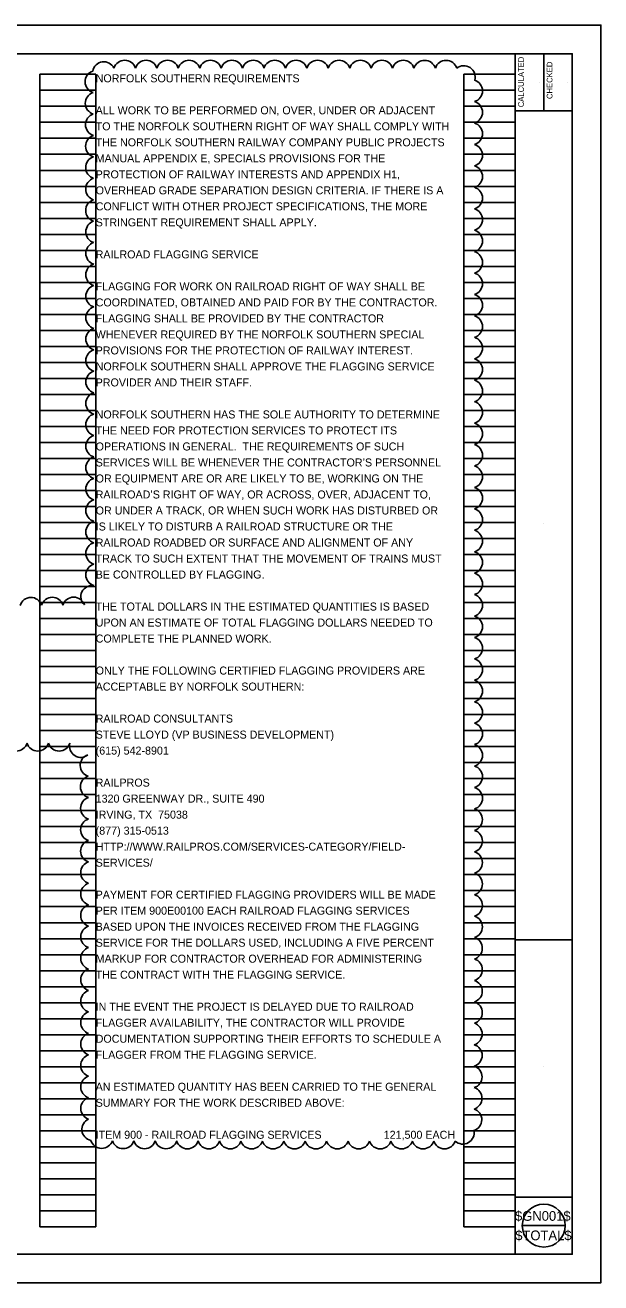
# Model space of a CAD drawing. Extents: x -9 to 100, y -25 to 48.
# Drawn here: x 24.71 to 34.78, y 0.1 to 22.1 of the extents above; entities that cross this region are included whole.
import ezdxf

# ---------------------------------------------------------------- set-up
doc = ezdxf.new("R2010")
doc.units = 0
for name, color, linetype in [('MU_Markup_Cloud', 7, 'Continuous'), ('SH_Border', 7, 'Continuous'), ('SH_Cut_Line', 7, 'Continuous'), ('SH_Data', 7, 'Continuous'), ('SH_Text', 7, 'Continuous')]:
    doc.layers.add(name, color=color, linetype=linetype)

msp = doc.modelspace()

# ---------------------------------------------------------------- linework, layer by layer
at = {"layer": 'MU_Markup_Cloud'}
for centre, radius, start, end in [((26.086, 21.264), 0.196, 25.5249, 170.5249), ((26.451, 21.289), 0.197, 17.5, 162.5), ((26.826, 21.289), 0.197, 17.5, 162.5), ((27.201, 21.289), 0.197, 17.5, 162.5), ((27.576, 21.289), 0.197, 17.5, 162.5), ((27.951, 21.289), 0.197, 17.5, 162.5), ((28.326, 21.289), 0.197, 17.5, 162.5), ((28.701, 21.289), 0.197, 17.5, 162.5), ((29.076, 21.289), 0.197, 17.5, 162.5), ((29.451, 21.289), 0.197, 17.4978, 162.4978), ((29.826, 21.289), 0.197, 17.4937, 162.4937), ((30.201, 21.289), 0.197, 17.4887, 162.4887), ((30.576, 21.289), 0.197, 17.4823, 162.4823), ((30.951, 21.289), 0.197, 17.4738, 162.4738), ((31.325, 21.289), 0.197, 17.4616, 162.4616), ((31.7, 21.288), 0.197, 17.4421, 162.4421), ((32.075, 21.288), 0.197, 17.402, 162.402), ((32.386, 21.194), 0.197, 343.7542, 128.7542), ((25.955, 21.11), 0.197, 108.4583, 253.4583), ((32.515, 20.951), 0.197, 287.5, 72.5), ((25.959, 20.734), 0.197, 107.9402, 252.9402), ((32.515, 20.576), 0.197, 287.5, 72.5), ((25.962, 20.359), 0.197, 107.7909, 252.7909), ((32.515, 20.201), 0.197, 287.5, 72.5), ((25.963, 19.984), 0.197, 107.7103, 252.7103), ((32.515, 19.826), 0.197, 287.5, 72.5), ((25.965, 19.609), 0.197, 107.6578, 252.6578), ((32.515, 19.451), 0.197, 287.5, 72.5), ((25.966, 19.234), 0.197, 107.6202, 252.6202), ((32.515, 19.076), 0.197, 287.5, 72.5), ((25.966, 18.859), 0.197, 107.5914, 252.5914), ((32.515, 18.701), 0.197, 287.5, 72.5), ((25.967, 18.484), 0.197, 107.5685, 252.5685), ((32.515, 18.326), 0.197, 287.5, 72.5), ((25.967, 18.109), 0.197, 107.5498, 252.5498), ((32.515, 17.951), 0.197, 287.5, 72.5), ((25.967, 17.734), 0.197, 107.534, 252.534), ((32.515, 17.577), 0.197, 287.5, 72.5), ((25.968, 17.359), 0.197, 107.5206, 252.5206), ((32.515, 17.202), 0.197, 287.5, 72.5), ((25.968, 16.984), 0.197, 107.5089, 252.5089), ((32.515, 16.827), 0.197, 287.5, 72.5), ((25.968, 16.609), 0.197, 107.5006, 252.5006), ((32.515, 16.452), 0.197, 287.5, 72.5), ((25.968, 16.234), 0.197, 107.5, 252.5), ((32.515, 16.077), 0.197, 287.5, 72.5), ((25.968, 15.859), 0.197, 107.5, 252.5), ((32.515, 15.702), 0.197, 287.5, 72.5), ((25.968, 15.484), 0.197, 107.5, 252.5), ((32.515, 15.327), 0.197, 287.5, 72.5), ((25.968, 15.11), 0.197, 107.5, 252.5), ((32.515, 14.952), 0.197, 287.5, 72.5), ((25.968, 14.735), 0.197, 107.5, 252.5), ((32.515, 14.577), 0.197, 287.5, 72.5), ((25.968, 14.36), 0.197, 107.5, 252.5), ((32.515, 14.202), 0.197, 287.5, 72.5), ((25.968, 13.985), 0.197, 107.5, 252.5), ((32.515, 13.827), 0.197, 287.5, 72.5), ((25.968, 13.61), 0.197, 107.5, 252.5), ((25.968, 13.235), 0.197, 107.5, 252.5), ((32.515, 13.452), 0.197, 287.5, 72.5), ((32.515, 13.077), 0.197, 287.5, 72.5), ((25.968, 12.86), 0.197, 107.5, 252.5), ((32.515, 12.702), 0.197, 287.5, 72.5), ((25.968, 12.485), 0.197, 107.5, 252.5), ((32.515, 12.327), 0.197, 287.5, 72.5), ((25.881, 12.103), 0.197, 81.8355, 226.8355), ((32.515, 11.952), 0.197, 287.4997, 72.4997), ((24.809, 11.893), 0.197, 17.7281, 162.7281), ((25.184, 11.895), 0.197, 17.84, 162.84), ((25.559, 11.898), 0.197, 18.1233, 163.1233), ((32.515, 11.577), 0.197, 287.4976, 72.4976), ((32.515, 11.202), 0.197, 287.4951, 72.4951), ((32.515, 10.828), 0.197, 287.4924, 72.4924), ((32.515, 10.453), 0.197, 287.4895, 72.4895), ((32.515, 10.078), 0.197, 287.4864, 72.4864), ((32.515, 9.703), 0.197, 287.4831, 72.4831), ((24.554, 9.599), 0.197, 197.5, 342.5), ((24.929, 9.599), 0.197, 197.5, 342.5), ((25.304, 9.599), 0.197, 197.5, 342.5), ((25.682, 9.489), 0.197, 165.0186, 310.0186), ((32.515, 9.328), 0.197, 287.4795, 72.4795), ((25.869, 9.152), 0.197, 108.1907, 253.1907), ((32.515, 8.953), 0.197, 287.4756, 72.4756), ((25.873, 8.777), 0.197, 107.8803, 252.8803), ((25.875, 8.402), 0.197, 107.7489, 252.7489), ((32.515, 8.578), 0.197, 287.4713, 72.4713), ((32.514, 8.203), 0.197, 287.4666, 72.4666), ((25.876, 8.027), 0.197, 107.6712, 252.6712), ((32.514, 7.828), 0.197, 287.4614, 72.4614), ((25.877, 7.652), 0.197, 107.6182, 252.6182), ((32.514, 7.453), 0.197, 287.4556, 72.4556), ((25.878, 7.277), 0.197, 107.5791, 252.5791), ((32.514, 7.078), 0.197, 287.4491, 72.4491), ((25.878, 6.902), 0.197, 107.5487, 252.5487), ((32.513, 6.703), 0.197, 287.4418, 72.4418), ((25.878, 6.527), 0.197, 107.5242, 252.5242), ((32.513, 6.328), 0.197, 287.4334, 72.4334), ((25.879, 6.152), 0.197, 107.5047, 252.5047), ((25.879, 5.777), 0.197, 107.5, 252.5), ((32.512, 5.953), 0.197, 287.4235, 72.4235), ((32.512, 5.578), 0.197, 287.4119, 72.4119), ((25.879, 5.402), 0.197, 107.5, 252.5), ((32.511, 5.203), 0.197, 287.3979, 72.3979), ((25.879, 5.027), 0.197, 107.5, 252.5), ((32.511, 4.829), 0.197, 287.3805, 72.3805), ((25.879, 4.652), 0.197, 107.5, 252.5), ((32.51, 4.454), 0.197, 287.358, 72.358), ((25.879, 4.277), 0.197, 107.5, 252.5), ((32.509, 4.079), 0.197, 287.3275, 72.3275), ((25.879, 3.902), 0.197, 107.5, 252.5), ((32.507, 3.704), 0.197, 287.2825, 72.2825), ((25.879, 3.527), 0.197, 107.5, 252.5), ((25.879, 3.152), 0.197, 107.5, 252.5), ((32.506, 3.329), 0.197, 287.2058, 72.2058), ((32.503, 2.954), 0.197, 287.0195, 72.0195), ((25.899, 2.785), 0.197, 113.7583, 258.7583), ((32.368, 2.725), 0.197, 226.9921, 11.9921), ((26.049, 2.649), 0.197, 196.7621, 341.7621), ((26.423, 2.645), 0.197, 197.1919, 342.1919), ((26.798, 2.644), 0.197, 197.3089, 342.3089), ((27.173, 2.643), 0.197, 197.3715, 342.3715), ((27.548, 2.642), 0.197, 197.4121, 342.4121), ((27.923, 2.641), 0.197, 197.4412, 342.4412), ((28.298, 2.641), 0.197, 197.4634, 342.4634), ((28.672, 2.641), 0.197, 197.481, 342.481), ((29.047, 2.641), 0.197, 197.4953, 342.4953), ((29.422, 2.641), 0.197, 197.5, 342.5), ((29.797, 2.641), 0.197, 197.5, 342.5), ((30.172, 2.641), 0.197, 197.5, 342.5), ((30.547, 2.641), 0.197, 197.5, 342.5), ((30.922, 2.641), 0.197, 197.5, 342.5), ((31.297, 2.641), 0.197, 197.5, 342.5), ((31.672, 2.641), 0.197, 197.5, 342.5), ((32.047, 2.641), 0.197, 197.5, 342.5)]:
    msp.add_arc(centre, radius, start, end, dxfattribs=at)
at = {"layer": 'SH_Border'}
for p, q in [((33.283, 0.601), (33.283, 21.601)), ((33.783, 21.601), (33.783, 20.601)), ((33.283, 20.601), (34.283, 20.601)), ((33.283, 6.101), (34.283, 6.101)), ((33.283, 1.601), (34.283, 1.601))]:
    msp.add_line(p, q, dxfattribs=at)
msp.add_lwpolyline([(2.783, 21.601), (34.283, 21.601), (34.283, 0.601), (2.783, 0.601)], close=True, dxfattribs=at)
at = {"layer": 'SH_Cut_Line'}
msp.add_lwpolyline([(0.783, 0.101), (34.783, 0.101), (34.783, 22.101), (0.783, 22.101)], close=True, dxfattribs=at)
at = {"layer": 'SH_Data'}
for p, q in [((24.963, 1.081), (24.963, 21.241)), ((24.963, 21.241), (25.943, 21.241)), ((25.943, 1.081), (25.943, 21.241)), ((32.383, 1.081), (32.383, 21.241)), ((32.383, 21.241), (33.283, 21.241)), ((33.283, 1.081), (33.283, 21.241)), ((24.963, 20.961), (25.943, 20.961)), ((32.383, 20.961), (33.283, 20.961)), ((33.703, 21.104), (33.703, 21.104)), ((34.203, 21.104), (34.203, 21.104)), ((24.963, 20.681), (25.943, 20.681)), ((32.383, 20.681), (33.283, 20.681)), ((24.963, 20.401), (25.943, 20.401)), ((32.383, 20.401), (33.283, 20.401)), ((24.963, 20.121), (25.943, 20.121)), ((32.383, 20.121), (33.283, 20.121)), ((24.963, 19.841), (25.943, 19.841)), ((32.383, 19.841), (33.283, 19.841)), ((24.963, 19.561), (25.943, 19.561)), ((32.383, 19.561), (33.283, 19.561)), ((24.963, 19.281), (25.943, 19.281)), ((32.383, 19.281), (33.283, 19.281)), ((24.963, 19.001), (25.943, 19.001)), ((32.383, 19.001), (33.283, 19.001)), ((24.963, 18.721), (25.943, 18.721)), ((32.383, 18.721), (33.283, 18.721)), ((24.963, 18.441), (25.943, 18.441)), ((32.383, 18.441), (33.283, 18.441)), ((24.963, 18.161), (25.943, 18.161)), ((32.383, 18.161), (33.283, 18.161)), ((24.963, 17.881), (25.943, 17.881)), ((32.383, 17.881), (33.283, 17.881)), ((24.963, 17.601), (25.943, 17.601)), ((32.383, 17.601), (33.283, 17.601)), ((24.963, 17.321), (25.943, 17.321)), ((32.383, 17.321), (33.283, 17.321)), ((24.963, 17.041), (25.943, 17.041)), ((32.383, 17.041), (33.283, 17.041)), ((24.963, 16.761), (25.943, 16.761)), ((32.383, 16.761), (33.283, 16.761)), ((24.963, 16.481), (25.943, 16.481)), ((32.383, 16.481), (33.283, 16.481)), ((24.963, 16.201), (25.943, 16.201)), ((32.383, 16.201), (33.283, 16.201)), ((24.963, 15.921), (25.943, 15.921)), ((32.383, 15.921), (33.283, 15.921)), ((24.963, 15.641), (25.943, 15.641)), ((32.383, 15.641), (33.283, 15.641)), ((24.963, 15.361), (25.943, 15.361)), ((32.383, 15.361), (33.283, 15.361)), ((24.963, 15.081), (25.943, 15.081)), ((32.383, 15.081), (33.283, 15.081)), ((24.963, 14.801), (25.943, 14.801)), ((32.383, 14.801), (33.283, 14.801)), ((24.963, 14.521), (25.943, 14.521)), ((32.383, 14.521), (33.283, 14.521)), ((24.963, 14.241), (25.943, 14.241)), ((32.383, 14.241), (33.283, 14.241)), ((24.963, 13.961), (25.943, 13.961)), ((32.383, 13.961), (33.283, 13.961)), ((24.963, 13.681), (25.943, 13.681)), ((32.383, 13.681), (33.283, 13.681)), ((24.963, 13.401), (25.943, 13.401)), ((32.383, 13.401), (33.283, 13.401)), ((33.783, 13.392), (33.783, 13.392)), ((24.963, 13.121), (25.943, 13.121)), ((32.383, 13.121), (33.283, 13.121)), ((24.963, 12.841), (25.943, 12.841)), ((32.383, 12.841), (33.283, 12.841)), ((24.963, 12.561), (25.943, 12.561)), ((32.383, 12.561), (33.283, 12.561)), ((24.963, 12.281), (25.943, 12.281)), ((32.383, 12.281), (33.283, 12.281)), ((24.963, 12.001), (25.943, 12.001)), ((32.383, 12.001), (33.283, 12.001)), ((24.963, 11.721), (25.943, 11.721)), ((32.383, 11.721), (33.283, 11.721)), ((24.963, 11.441), (25.943, 11.441)), ((32.383, 11.441), (33.283, 11.441)), ((24.963, 11.161), (25.943, 11.161)), ((32.383, 11.161), (33.283, 11.161)), ((24.963, 10.881), (25.943, 10.881)), ((32.383, 10.881), (33.283, 10.881)), ((24.963, 10.601), (25.943, 10.601)), ((32.383, 10.601), (33.283, 10.601)), ((24.963, 10.321), (25.943, 10.321)), ((32.383, 10.321), (33.283, 10.321)), ((24.963, 10.041), (25.943, 10.041)), ((32.383, 10.041), (33.283, 10.041)), ((24.963, 9.761), (25.943, 9.761)), ((32.383, 9.761), (33.283, 9.761)), ((24.963, 9.481), (25.943, 9.481)), ((32.383, 9.481), (33.283, 9.481)), ((24.963, 9.201), (25.943, 9.201)), ((32.383, 9.201), (33.283, 9.201)), ((24.963, 8.921), (25.943, 8.921)), ((32.383, 8.921), (33.283, 8.921)), ((24.963, 8.641), (25.943, 8.641)), ((32.383, 8.641), (33.283, 8.641)), ((24.963, 8.361), (25.943, 8.361)), ((32.383, 8.361), (33.283, 8.361)), ((24.963, 8.081), (25.943, 8.081)), ((32.383, 8.081), (33.283, 8.081)), ((24.963, 7.801), (25.943, 7.801)), ((32.383, 7.801), (33.283, 7.801)), ((24.963, 7.521), (25.943, 7.521)), ((32.383, 7.521), (33.283, 7.521)), ((24.963, 7.241), (25.943, 7.241)), ((32.383, 7.241), (33.283, 7.241)), ((24.963, 6.961), (25.943, 6.961)), ((32.383, 6.961), (33.283, 6.961)), ((24.963, 6.681), (25.943, 6.681)), ((32.383, 6.681), (33.283, 6.681)), ((24.963, 6.401), (25.943, 6.401)), ((32.383, 6.401), (33.283, 6.401)), ((24.963, 6.121), (25.943, 6.121)), ((32.383, 6.121), (33.283, 6.121)), ((24.963, 5.841), (25.943, 5.841)), ((32.383, 5.841), (33.283, 5.841)), ((24.963, 5.561), (25.943, 5.561)), ((32.383, 5.561), (33.283, 5.561)), ((24.963, 5.281), (25.943, 5.281)), ((32.383, 5.281), (33.283, 5.281)), ((24.963, 5.001), (25.943, 5.001)), ((32.383, 5.001), (33.283, 5.001)), ((24.963, 4.721), (25.943, 4.721)), ((32.383, 4.721), (33.283, 4.721)), ((24.963, 4.441), (25.943, 4.441)), ((32.383, 4.441), (33.283, 4.441)), ((24.963, 4.161), (25.943, 4.161)), ((32.383, 4.161), (33.283, 4.161)), ((24.963, 3.881), (25.943, 3.881)), ((32.383, 3.881), (33.283, 3.881)), ((33.783, 3.892), (33.783, 3.892)), ((24.963, 3.601), (25.943, 3.601)), ((32.383, 3.601), (33.283, 3.601)), ((24.963, 3.321), (25.943, 3.321)), ((32.383, 3.321), (33.283, 3.321)), ((24.963, 3.041), (25.943, 3.041)), ((32.383, 3.041), (33.283, 3.041)), ((24.963, 2.761), (25.943, 2.761)), ((32.383, 2.761), (33.283, 2.761)), ((24.963, 2.481), (25.943, 2.481)), ((32.383, 2.481), (33.283, 2.481)), ((24.963, 2.201), (25.943, 2.201)), ((32.383, 2.201), (33.283, 2.201)), ((24.963, 1.921), (25.943, 1.921)), ((32.383, 1.921), (33.283, 1.921)), ((24.963, 1.641), (25.943, 1.641)), ((32.383, 1.641), (33.283, 1.641)), ((24.963, 1.361), (25.943, 1.361)), ((32.383, 1.361), (33.283, 1.361)), ((33.408, 1.101), (34.158, 1.101)), ((33.783, 1.186), (33.783, 1.186)), ((24.963, 1.081), (25.943, 1.081)), ((32.383, 1.081), (33.283, 1.081)), ((33.783, 0.846), (33.783, 0.846))]:
    msp.add_line(p, q, dxfattribs=at)
msp.add_circle((33.783, 1.101), 0.375, dxfattribs=at)

# ---------------------------------------------------------------- texts
for s, p in [('CALCULATED', (33.436, 20.665)), ('CHECKED', (33.936, 20.809))]:
    msp.add_text(s, height=0.1, rotation=90, dxfattribs=at).set_placement(p)
at = {"layer": 'SH_Text'}
for s, height, p in [('NORFOLK SOUTHERN REQUIREMENTS', 0.14, (25.943, 21.101)), ('ALL WORK TO BE PERFORMED ON, OVER, UNDER OR ADJACENT ', 0.14, (25.943, 20.541)), ('TO THE NORFOLK SOUTHERN RIGHT OF WAY SHALL COMPLY WITH ', 0.14, (25.943, 20.261)), ('THE NORFOLK SOUTHERN RAILWAY COMPANY PUBLIC PROJECTS ', 0.14, (25.943, 19.981)), ('MANUAL APPENDIX E, SPECIALS PROVISIONS FOR THE ', 0.14, (25.943, 19.701)), ('PROTECTION OF RAILWAY INTERESTS AND APPENDIX H1, ', 0.14, (25.943, 19.421)), ('OVERHEAD GRADE SEPARATION DESIGN CRITERIA. IF THERE IS A ', 0.14, (25.943, 19.141)), ('CONFLICT WITH OTHER PROJECT SPECIFICATIONS, THE MORE ', 0.14, (25.943, 18.861)), ('STRINGENT REQUIREMENT SHALL APPLY.', 0.14, (25.943, 18.581)), ('RAILROAD FLAGGING SERVICE', 0.14, (25.943, 18.021)), ('FLAGGING FOR WORK ON RAILROAD RIGHT OF WAY SHALL BE ', 0.14, (25.943, 17.461)), ('COORDINATED, OBTAINED AND PAID FOR BY THE CONTRACTOR.  ', 0.14, (25.943, 17.181)), ('FLAGGING SHALL BE PROVIDED BY THE CONTRACTOR ', 0.14, (25.943, 16.901)), ('WHENEVER REQUIRED BY THE NORFOLK SOUTHERN SPECIAL ', 0.14, (25.943, 16.621)), ('PROVISIONS FOR THE PROTECTION OF RAILWAY INTEREST.  ', 0.14, (25.943, 16.341)), ('NORFOLK SOUTHERN SHALL APPROVE THE FLAGGING SERVICE ', 0.14, (25.943, 16.061)), ('PROVIDER AND THEIR STAFF.', 0.14, (25.943, 15.781)), ('NORFOLK SOUTHERN HAS THE SOLE AUTHORITY TO DETERMINE ', 0.14, (25.943, 15.221)), ('THE NEED FOR PROTECTION SERVICES TO PROTECT ITS ', 0.14, (25.943, 14.941)), ('OPERATIONS IN GENERAL.  THE REQUIREMENTS OF SUCH ', 0.14, (25.943, 14.661)), ('SERVICES WILL BE WHENEVER THE CONTRACTOR’S PERSONNEL ', 0.14, (25.943, 14.381)), ('OR EQUIPMENT ARE OR ARE LIKELY TO BE, WORKING ON THE ', 0.14, (25.943, 14.101)), ('RAILROAD’S RIGHT OF WAY, OR ACROSS, OVER, ADJACENT TO, ', 0.14, (25.943, 13.821)), ('OR UNDER A TRACK, OR WHEN SUCH WORK HAS DISTURBED OR ', 0.14, (25.943, 13.541)), ('IS LIKELY TO DISTURB A RAILROAD STRUCTURE OR THE ', 0.14, (25.943, 13.261)), ('RAILROAD ROADBED OR SURFACE AND ALIGNMENT OF ANY ', 0.14, (25.943, 12.981)), ('TRACK TO SUCH EXTENT THAT THE MOVEMENT OF TRAINS MUST ', 0.14, (25.943, 12.701)), ('BE CONTROLLED BY FLAGGING. ', 0.14, (25.943, 12.421)), ('THE TOTAL DOLLARS IN THE ESTIMATED QUANTITIES IS BASED ', 0.14, (25.943, 11.861)), ('UPON AN ESTIMATE OF TOTAL FLAGGING DOLLARS NEEDED TO ', 0.14, (25.943, 11.581)), ('COMPLETE THE PLANNED WORK. ', 0.14, (25.943, 11.301)), ('ONLY THE FOLLOWING CERTIFIED FLAGGING PROVIDERS ARE ', 0.14, (25.943, 10.741)), ('ACCEPTABLE BY NORFOLK SOUTHERN: ', 0.14, (25.943, 10.461)), ('RAILROAD CONSULTANTS ', 0.14, (25.943, 9.901)), ('STEVE LLOYD (VP BUSINESS DEVELOPMENT)  ', 0.14, (25.943, 9.621)), ('(615) 542-8901    ', 0.14, (25.943, 9.341)), ('RAILPROS ', 0.14, (25.943, 8.781)), ('1320 GREENWAY DR., SUITE 490 ', 0.14, (25.943, 8.501)), ('IRVING, TX  75038 ', 0.14, (25.943, 8.221)), ('(877) 315-0513 ', 0.14, (25.943, 7.941)), ('HTTP://WWW.RAILPROS.COM/SERVICES-CATEGORY/FIELD-', 0.14, (25.943, 7.661)), ('SERVICES/ ', 0.14, (25.943, 7.381)), ('PAYMENT FOR CERTIFIED FLAGGING PROVIDERS WILL BE MADE ', 0.14, (25.943, 6.821)), ('PER ITEM 900E00100 EACH RAILROAD FLAGGING SERVICES ', 0.14, (25.943, 6.541)), ('BASED UPON THE INVOICES RECEIVED FROM THE FLAGGING ', 0.14, (25.943, 6.261)), ('SERVICE FOR THE DOLLARS USED, INCLUDING A FIVE PERCENT ', 0.14, (25.943, 5.981)), ('MARKUP FOR CONTRACTOR OVERHEAD FOR ADMINISTERING ', 0.14, (25.943, 5.701)), ('THE CONTRACT WITH THE FLAGGING SERVICE.  ', 0.14, (25.943, 5.421)), ('IN THE EVENT THE PROJECT IS DELAYED DUE TO RAILROAD ', 0.14, (25.943, 4.861)), ('FLAGGER AVAILABILITY, THE CONTRACTOR WILL PROVIDE ', 0.14, (25.943, 4.581)), ('DOCUMENTATION SUPPORTING THEIR EFFORTS TO SCHEDULE A ', 0.14, (25.943, 4.301)), ('FLAGGER FROM THE FLAGGING SERVICE.', 0.14, (25.943, 4.021)), ('AN ESTIMATED QUANTITY HAS BEEN CARRIED TO THE GENERAL ', 0.14, (25.943, 3.461)), ('SUMMARY FOR THE WORK DESCRIBED ABOVE:', 0.14, (25.943, 3.181)), ('ITEM 900 - RAILROAD FLAGGING SERVICES', 0.14, (25.943, 2.621)), ('121,500 EACH', 0.14, (30.983, 2.621)), ('$GN001$', 0.17, (33.281, 1.186)), ('$TOTAL$', 0.17, (33.285, 0.846))]:
    msp.add_text(s, height=height, dxfattribs=at).set_placement(p)

doc.saveas('drawing.dxf')
